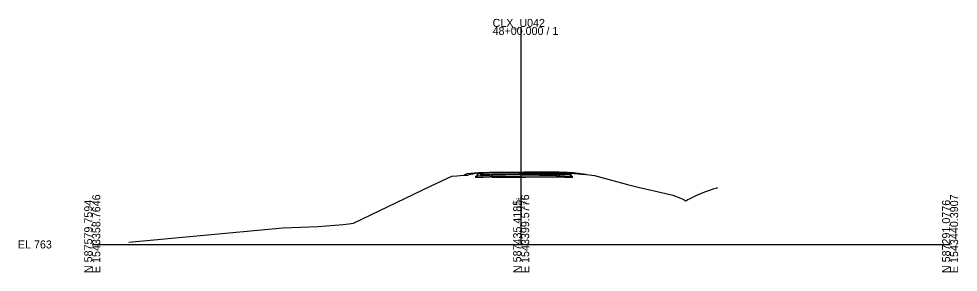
# Model space of a CAD drawing. Extents: x -26 to 1603, y -10 to 5557.
# Drawn here: x -25.7 to 302.8, y 4490.3 to 4578.9 of the extents above; entities that cross this region are included whole.
import ezdxf

# ---------------------------------------------------------------- set-up
doc = ezdxf.new("R2010")
doc.units = 0
for name, color, linetype in [('GK_Cells', 7, 'Continuous'), ('XS_P_Annotation', 7, 'Continuous'), ('XS_P_Earthwork_Shapes', 7, 'Continuous'), ('XS_P_Finished_Grade', 7, 'Continuous'), ('XS_P_Pavt_Layers', 7, 'Continuous'), ('XS_P_Pavt_Surface', 7, 'Continuous'), ('XS_P_Shoulder_Layers', 7, 'Continuous'), ('XS_P_Shoulder_Surface', 7, 'Continuous'), ('XS_P_Subgrade', 7, 'Continuous'), ('XS_X_Ground_Line', 7, 'Continuous'), ('XS_X_Pavt', 7, 'Continuous')]:
    doc.layers.add(name, color=color, linetype=linetype)

msp = doc.modelspace()

# ---------------------------------------------------------------- linework, layer by layer
at = {"layer": 'GK_Cells'}
for p, q in [((150, 4500), (150, 4576.01)), ((0, 4500), (150, 4500)), ((150, 4500), (300, 4500))]:
    msp.add_line(p, q, dxfattribs=at)
at = {"layer": 'XS_P_Earthwork_Shapes'}
for points in [[(131, 4524.63), (130.1, 4524.19), (131.29, 4524.25), (131.8, 4524.39), (133.04, 4524.69), (133.77, 4524.86)], [(130.1, 4524.19), (131.29, 4524.25), (131.8, 4524.39), (133.04, 4524.69), (133.77, 4524.86), (131, 4524.63)], [(130.1, 4524.19), (131.29, 4524.25), (131.8, 4524.39), (133.04, 4524.69), (133.77, 4524.86), (131, 4524.63)], [(139.79, 4524.4), (139.79, 4523.62), (139.08, 4523.61), (134.2, 4523.41), (134.2, 4523.92), (134.7, 4523.94), (134.7, 4524.69), (135.03, 4524.7), (135.03, 4524.97), (133.77, 4524.86), (134.47, 4525.03), (135.72, 4525.06), (135.72, 4524.31), (138.02, 4524.36), (138.85, 4524.38)], [(138.02, 4524.36), (138.85, 4524.38), (139.79, 4524.4), (139.79, 4523.62), (139.08, 4523.61), (134.2, 4523.41), (134.2, 4523.92), (134.7, 4523.94), (134.7, 4524.69), (135.03, 4524.7), (135.03, 4524.97), (133.77, 4524.86), (134.47, 4525.03), (135.72, 4525.06), (135.72, 4524.31)], [(138.02, 4524.36), (138.85, 4524.38), (139.79, 4524.4), (139.79, 4523.62), (139.08, 4523.61), (134.2, 4523.41), (134.2, 4523.92), (134.7, 4523.94), (134.7, 4524.69), (135.03, 4524.7), (135.03, 4524.97), (133.77, 4524.86), (134.47, 4525.03), (135.72, 4525.06), (135.72, 4524.31)], [(163.15, 4525.33), (166.23, 4525.29), (167.04, 4525.19), (167.04, 4524.93), (167.04, 4524.66), (167.04, 4524.44), (166.23, 4524.54), (163.31, 4524.58), (163.15, 4524.58), (162.57, 4524.59), (151.5, 4524.57), (151.08, 4524.57), (150, 4524.56), (149.13, 4524.54), (139.79, 4524.4), (138.85, 4524.38), (138.02, 4524.36), (135.72, 4524.31), (135.72, 4525.06), (138.02, 4525.11), (138.85, 4525.13), (149.13, 4525.29), (150, 4525.31), (151.08, 4525.32), (151.5, 4525.32), (162.57, 4525.34)], [(135.72, 4525.06), (138.02, 4525.11), (138.85, 4525.13), (149.13, 4525.29), (150, 4525.31), (151.08, 4525.32), (151.5, 4525.32), (162.57, 4525.34), (163.15, 4525.33), (166.23, 4525.29), (167.04, 4525.19), (167.04, 4524.93), (167.04, 4524.66), (167.04, 4524.44), (166.23, 4524.54), (163.31, 4524.58), (163.15, 4524.58), (162.57, 4524.59), (151.5, 4524.57), (151.08, 4524.57), (150, 4524.56), (149.13, 4524.54), (139.79, 4524.4), (138.85, 4524.38), (138.02, 4524.36), (135.72, 4524.31)], [(135.72, 4525.06), (138.02, 4525.11), (138.85, 4525.13), (149.13, 4525.29), (150, 4525.31), (151.08, 4525.32), (151.5, 4525.32), (162.57, 4525.34), (163.15, 4525.33), (166.23, 4525.29), (167.04, 4525.19), (167.04, 4524.93), (167.04, 4524.66), (167.04, 4524.44), (166.23, 4524.54), (163.31, 4524.58), (163.15, 4524.58), (162.57, 4524.59), (151.5, 4524.57), (151.08, 4524.57), (150, 4524.56), (149.13, 4524.54), (139.79, 4524.4), (138.85, 4524.38), (138.02, 4524.36), (135.72, 4524.31)], [(162.57, 4523.59), (163.15, 4523.58), (163.31, 4523.58), (163.31, 4524.58), (163.15, 4524.58), (162.57, 4524.59), (151.5, 4524.57), (151.08, 4524.57), (150, 4524.56), (149.13, 4524.54), (139.79, 4524.4), (139.79, 4523.62), (150, 4523.78), (162.41, 4523.59)], [(162.57, 4523.59), (163.15, 4523.58), (163.31, 4523.58), (163.31, 4524.58), (163.15, 4524.58), (162.57, 4524.59), (151.5, 4524.57), (151.08, 4524.57), (150, 4524.56), (149.13, 4524.54), (139.79, 4524.4), (139.79, 4523.62), (150, 4523.78), (162.41, 4523.59)], [(162.57, 4523.59), (163.15, 4523.58), (163.31, 4523.58), (163.31, 4524.58), (163.15, 4524.58), (162.57, 4524.59), (151.5, 4524.57), (151.08, 4524.57), (150, 4524.56), (149.13, 4524.54), (139.79, 4524.4), (139.79, 4523.62), (150, 4523.78), (162.41, 4523.59)], [(162.57, 4523.59), (163.15, 4523.58), (163.31, 4523.58), (163.31, 4524.58), (166.23, 4524.54), (167.04, 4524.44), (167.04, 4524.66), (167.37, 4524.65), (167.37, 4523.9), (167.87, 4523.88), (167.87, 4523.38), (162.73, 4523.58), (162.41, 4523.59)], [(162.57, 4523.59), (163.15, 4523.58), (163.31, 4523.58), (163.31, 4524.58), (166.23, 4524.54), (167.04, 4524.44), (167.04, 4524.66), (167.37, 4524.65), (167.37, 4523.9), (167.87, 4523.88), (167.87, 4523.38), (162.73, 4523.58), (162.41, 4523.59)], [(162.57, 4523.59), (163.15, 4523.58), (163.31, 4523.58), (163.31, 4524.58), (166.23, 4524.54), (167.04, 4524.44), (167.04, 4524.66), (167.37, 4524.65), (167.37, 4523.9), (167.87, 4523.88), (167.87, 4523.38), (162.73, 4523.58), (162.41, 4523.59)], [(167.04, 4524.93), (172.64, 4524.46), (168.33, 4525.02), (167.04, 4525.19)], [(167.04, 4525.19), (168.33, 4525.02), (172.64, 4524.46), (167.04, 4524.93)], [(167.04, 4525.19), (168.33, 4525.02), (172.64, 4524.46), (167.04, 4524.93)]]:
    msp.add_lwpolyline(points, close=True, dxfattribs=at)
at = {"layer": 'XS_P_Finished_Grade'}
for p, q in [((131, 4524.63), (130.1, 4524.19)), ((135.03, 4524.97), (131, 4524.63)), ((167.04, 4524.93), (172.64, 4524.46))]:
    msp.add_line(p, q, dxfattribs=at)
at = {"layer": 'XS_P_Pavt_Layers'}
for p, q in [((134.2, 4523.92), (134.2, 4523.41)), ((134.7, 4524.69), (134.7, 4523.94)), ((135.03, 4524.97), (135.03, 4524.7)), ((150, 4525.18), (139.04, 4525.01)), ((150, 4525.03), (139.04, 4524.86)), ((150.02, 4524.28), (139.05, 4524.11)), ((149.98, 4524.28), (162.75, 4524.08)), ((150, 4525.18), (162.77, 4524.98)), ((150, 4525.03), (162.77, 4524.83)), ((167.04, 4524.93), (167.04, 4524.66)), ((167.37, 4524.65), (167.37, 4523.9)), ((150.02, 4523.78), (139.06, 4523.61)), ((149.98, 4523.78), (162.75, 4523.58)), ((167.87, 4523.88), (167.87, 4523.38))]:
    msp.add_line(p, q, dxfattribs=at)
at = {"layer": 'XS_P_Pavt_Surface'}
for q in [(139.03, 4525.13), (162.77, 4525.1)]:
    msp.add_line((150, 4525.31), q, dxfattribs=at)
at = {"layer": 'XS_P_Shoulder_Layers'}
for p, q in [((139.07, 4524.11), (134.2, 4523.92)), ((139.04, 4524.86), (134.7, 4524.69)), ((139.04, 4525.01), (135.04, 4524.85)), ((162.73, 4524.08), (167.87, 4523.88)), ((162.76, 4524.83), (167.37, 4524.65)), ((162.77, 4524.98), (167.03, 4524.81)), ((139.09, 4523.61), (134.2, 4523.41)), ((162.71, 4523.58), (167.87, 4523.38))]:
    msp.add_line(p, q, dxfattribs=at)
at = {"layer": 'XS_P_Shoulder_Surface'}
for p, q in [((139.03, 4525.13), (135.03, 4524.97)), ((162.77, 4525.1), (167.04, 4524.93))]:
    msp.add_line(p, q, dxfattribs=at)
at = {"layer": 'XS_P_Subgrade'}
msp.add_lwpolyline([(135.03, 4524.97), (135.03, 4524.7), (134.7, 4524.69), (134.7, 4523.94), (134.2, 4523.92), (134.2, 4523.41), (139.08, 4523.61), (150, 4523.78), (162.73, 4523.58), (167.87, 4523.38), (167.87, 4523.88), (167.37, 4523.9), (167.37, 4524.65), (167.04, 4524.66), (167.04, 4524.93)], dxfattribs=at)
at = {"layer": 'XS_X_Ground_Line'}
msp.add_lwpolyline([(12.8, 4500.85), (66.66, 4505.76), (78.98, 4506.29), (87.78, 4507.01), (89.69, 4507.21), (91.37, 4507.4), (118.57, 4520.45), (125.78, 4523.92), (127.49, 4524.03), (129.86, 4524.17), (131.29, 4524.25), (131.8, 4524.39), (133.04, 4524.69), (134.47, 4525.03), (138.02, 4525.11), (138.85, 4525.13), (149.13, 4525.29), (150, 4525.31), (151.08, 4525.32), (151.5, 4525.32), (162.57, 4525.34), (163.15, 4525.33), (166.23, 4525.29), (168.33, 4525.02), (175.67, 4524.07), (187.17, 4520.98), (191.34, 4519.85), (200.64, 4517.79), (203.05, 4517.24), (203.95, 4516.9), (206.29, 4516), (206.98, 4515.56), (207.54, 4515.23), (208.28, 4515.66), (208.83, 4515.97), (211.95, 4517.4), (214.56, 4518.5), (215.22, 4518.73), (216.28, 4519.09), (217.13, 4519.38), (218.16, 4519.68), (218.81, 4519.86)], dxfattribs=at)
at = {"layer": 'XS_X_Pavt'}
for p, q in [((135.72, 4525.06), (135.72, 4524.31)), ((135.72, 4524.31), (138.02, 4524.36)), ((138.02, 4524.36), (138.85, 4524.38)), ((138.85, 4524.38), (139.79, 4524.4)), ((139.79, 4524.4), (149.13, 4524.54)), ((139.79, 4524.4), (139.79, 4523.4)), ((149.13, 4524.54), (150, 4524.56)), ((150, 4524.56), (151.08, 4524.57)), ((151.08, 4524.57), (151.5, 4524.57)), ((151.5, 4524.57), (162.57, 4524.59)), ((162.57, 4524.59), (163.15, 4524.58)), ((163.15, 4524.58), (163.31, 4524.58)), ((163.31, 4524.58), (166.23, 4524.54)), ((163.31, 4524.58), (163.31, 4523.58)), ((166.23, 4524.54), (167.04, 4524.44)), ((167.04, 4525.19), (167.04, 4524.44)), ((139.79, 4523.4), (149.13, 4523.54)), ((149.13, 4523.54), (150, 4523.56)), ((150, 4523.56), (151.08, 4523.57)), ((151.08, 4523.57), (151.5, 4523.57)), ((151.5, 4523.57), (162.57, 4523.59)), ((162.57, 4523.59), (163.15, 4523.58)), ((163.15, 4523.58), (163.31, 4523.58))]:
    msp.add_line(p, q, dxfattribs=at)

# ---------------------------------------------------------------- texts
at = {"layer": 'GK_Cells'}
for s, p in [('CLX_U042', (140, 4576.01)), ('48+00.000 / 1', (140, 4573.21)), ('EL 763', (-26, 4498.6))]:
    msp.add_text(s, height=2.8, dxfattribs=at).set_placement(p)
for s, p in [('N 587579.7594', (0, 4490)), ('E 1543358.7646', (2.8, 4490)), ('N 587435.4185', (150, 4490)), ('E 1543399.5776', (152.8, 4490)), ('N 587291.0776', (300, 4490)), ('E 1543440.3907', (302.8, 4490))]:
    msp.add_text(s, height=2.8, rotation=90, dxfattribs=at).set_placement(p)
at = {"layer": 'XS_P_Annotation'}
for s, height, p in [('48+00.00', 0.9, (146.85, 4514.05)), ('788.30', 0.7, (148.28, 4515.55)), ('788.31', 0.7, (148.42, 4512.75))]:
    msp.add_text(s, height=height, dxfattribs=at).set_placement(p)

doc.saveas('drawing.dxf')
